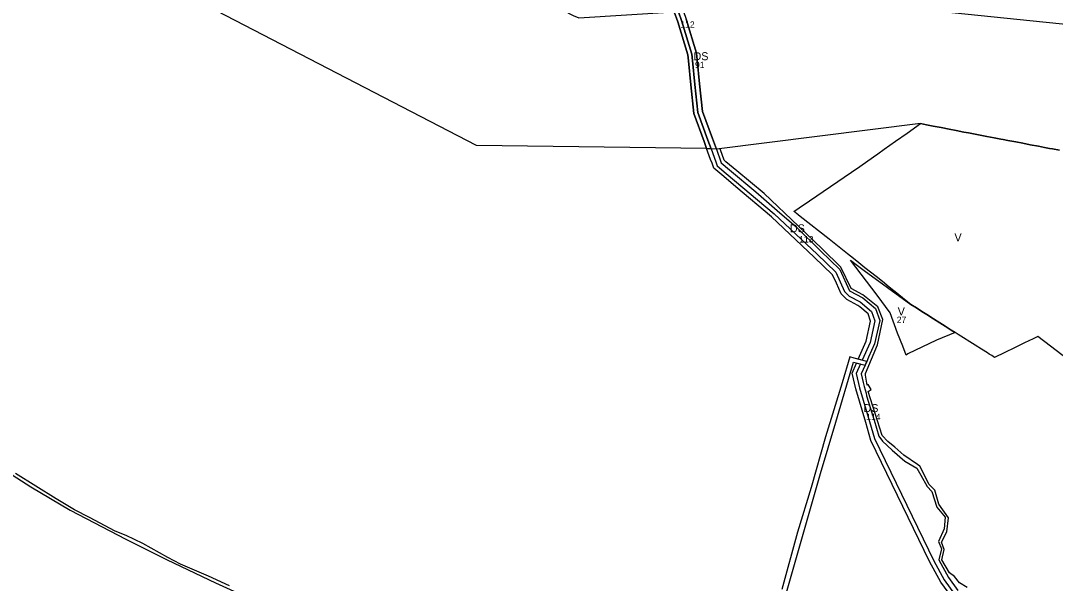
# Model space of a CAD drawing. Extents: x -521621 to -516769, y -1190068 to -1185078.
# Drawn here: x -520820 to -519528, y -1188202 to -1187500 of the extents above; entities that cross this region are included whole.
import ezdxf

# ---------------------------------------------------------------- set-up
doc = ezdxf.new("R2010")
doc.units = 0
for name, color, linetype in [('fpl_id', 7, 'Continuous'), ('v_infrastr_n', 7, 'Continuous'), ('v_infrastr_s', 7, 'Continuous'), ('voda_s', 7, 'Continuous'), ('vyroba_n', 7, 'Continuous'), ('vyroba_s', 7, 'Continuous')]:
    doc.layers.add(name, color=color, linetype=linetype)

msp = doc.modelspace()

# ---------------------------------------------------------------- linework, layer by layer
at = {"layer": 'v_infrastr_n'}
for points in [[(-520849, -1187150.2), (-520815.2, -1187153.9), (-520804.3, -1187155.1), (-520795.3, -1187156), (-520786.2, -1187157), (-520784.9, -1187157.2), (-520159, -1187477.9), (-520132.3, -1187491.8), (-520130, -1187493), (-520122.9, -1187496.1), (-520003.6, -1187488.8), (-519999.4, -1187501.1), (-519986.8, -1187542.4), (-519985.9, -1187549.9), (-519983.1, -1187579.6), (-519979.3, -1187615.3), (-519966.4, -1187650.5), (-519963.3, -1187659), (-520250.8, -1187655.6), (-520830.3, -1187354.9)], [(-519790.9, -1187475.7), (-519421.5, -1187513.5)], [(-519998.5, -1187488.4), (-519994.7, -1187499.6), (-519981.9, -1187541.3), (-519980.9, -1187549.3), (-519978.1, -1187579.2), (-519974.4, -1187614.2), (-519961.7, -1187648.8), (-519957.8, -1187659.5), (-519963.3, -1187659), (-519966.4, -1187650.5), (-519979.3, -1187615.3), (-519983.1, -1187579.6), (-519985.9, -1187549.9), (-519986.8, -1187542.4), (-519999.4, -1187501.1), (-520003.6, -1187488.8)], [(-519522.7, -1187661.3), (-519531.3, -1187659.7), (-519535.2, -1187659), (-519541.3, -1187657.8), (-519548.9, -1187656.4), (-519559.1, -1187654.4), (-519568.5, -1187652.6), (-519577.2, -1187651), (-519587, -1187649.1), (-519592.9, -1187647.9), (-519595.9, -1187647.4), (-519604.1, -1187645.8), (-519613.4, -1187644), (-519623.8, -1187642), (-519636, -1187639.7), (-519642, -1187638.6), (-519651.6, -1187636.7), (-519660.2, -1187635.1), (-519670.3, -1187633.1), (-519680.2, -1187631.2), (-519688.7, -1187629.6), (-519696.3, -1187628.1), (-519951.1, -1187660.2), (-519956.1, -1187646.7), (-519968.5, -1187612.8), (-519972.2, -1187578.6), (-519974.9, -1187548.7), (-519976, -1187540.1), (-519989, -1187497.8)], [(-519656.9, -1188219.1), (-519670.6, -1188200.3), (-519684.7, -1188174.4), (-519758, -1188023.6), (-519764.6, -1188001.2), (-519777.1, -1187959.1), (-519781.6, -1187939.4), (-519776, -1187926.9), (-519771.1, -1187928.1), (-519776.4, -1187939.9), (-519772.2, -1187957.8), (-519759.8, -1187999.7), (-519753.6, -1188021), (-519679.4, -1188173.7), (-519666.4, -1188197.6), (-519653.5, -1188215.3)]]:
    msp.add_lwpolyline(points, dxfattribs=at)
for points in [[(-519992.3, -1187488.1), (-519989, -1187497.8), (-519976, -1187540.1), (-519974.9, -1187548.7), (-519972.2, -1187578.6), (-519968.5, -1187612.8), (-519956.1, -1187646.7), (-519951.1, -1187660.2), (-519957.8, -1187659.5), (-519961.7, -1187648.8), (-519974.4, -1187614.2), (-519978.1, -1187579.2), (-519980.9, -1187549.3), (-519981.9, -1187541.3), (-519994.7, -1187499.6), (-519998.5, -1187488.4)], [(-519957.8, -1187659.5), (-519951.9, -1187675.7), (-519950, -1187680.7), (-519938.7, -1187690.2), (-519879.1, -1187740.9), (-519825.4, -1187791.1), (-519801.9, -1187813.7), (-519790.9, -1187837.6), (-519785.2, -1187843.5), (-519771.6, -1187850.7), (-519757.5, -1187862.4), (-519753.3, -1187874.2), (-519759.1, -1187901.2), (-519769.1, -1187923.5), (-519774, -1187922.2), (-519763.9, -1187899.7), (-519758.5, -1187874.5), (-519761.7, -1187865.3), (-519772, -1187856.8), (-519774.4, -1187854.9), (-519788.2, -1187847.5), (-519795.1, -1187840.5), (-519801.2, -1187827.2), (-519806.1, -1187816.7), (-519828.8, -1187794.7), (-519882.4, -1187744.6), (-519926.7, -1187707), (-519941.9, -1187694.1), (-519954.2, -1187683.7), (-519956.5, -1187677.4), (-519958.3, -1187672.7), (-519963.3, -1187659)]]:
    msp.add_lwpolyline(points, close=True, dxfattribs=at)
at = {"layer": 'v_infrastr_s'}
for points in [[(-519972.8, -1188669.2), (-519973.5, -1188653.5), (-519964.5, -1188604.5), (-519948, -1188528.1), (-519928, -1188459.1), (-519913.3, -1188406), (-519897.6, -1188334.5), (-519884, -1188283.9), (-519860.2, -1188201.7), (-519839.4, -1188128.8), (-519821, -1188064.9), (-519801.9, -1188000.7), (-519780, -1187925.9), (-519765.3, -1187929.6), (-519763.2, -1187925), (-519779.1, -1187921)], [(-519784.5, -1187919.3), (-519794, -1187951.7), (-519814.9, -1188019), (-519832.9, -1188082.4), (-519849.7, -1188138.1), (-519869.3, -1188209.7)], [(-519779.1, -1187921), (-519784.5, -1187919.3)], [(-520849.9, -1188054.2), (-520807.5, -1188081.5), (-520758.2, -1188110.4), (-520688.8, -1188146.6), (-520637.2, -1188172.7), (-520576.6, -1188201.3), (-520525.5, -1188224.7)], [(-520559, -1188204.8), (-520585.4, -1188193.1), (-520620.3, -1188177.8), (-520636.3, -1188169.8), (-520667.4, -1188152.3), (-520688.3, -1188142.3), (-520701.8, -1188136.6), (-520733.9, -1188119.6), (-520752.8, -1188110.2), (-520775.5, -1188096.2), (-520826.5, -1188064.8)]]:
    msp.add_lwpolyline(points, dxfattribs=at)
at = {"layer": 'voda_s'}
for points in [[(-519946, -1187660.7), (-519946.4, -1187659.6), (-519951.1, -1187660.2)], [(-519951.1, -1187660.2), (-519945.5, -1187675.7)], [(-519939.1, -1187675.7), (-519941.2, -1187673.9), (-519946, -1187660.7)], [(-519945.5, -1187675.7), (-519944.9, -1187677.2), (-519934.8, -1187685.7), (-519901.9, -1187713.3), (-519875.1, -1187736.4), (-519851.3, -1187757), (-519821.2, -1187786.7), (-519796.9, -1187810.2), (-519784.7, -1187837), (-519768.2, -1187845.7), (-519752.4, -1187858.8), (-519747.1, -1187873.8), (-519753.4, -1187903.1), (-519760.9, -1187919.7), (-519763.2, -1187925), (-519765.3, -1187929.6), (-519770.1, -1187940.5), (-519767.8, -1187951.4), (-519766.4, -1187956.3), (-519764.2, -1187964.5), (-519763.4, -1187967.8), (-519754.1, -1187998.1), (-519748.2, -1188018), (-519743.4, -1188024.4), (-519731.6, -1188035.5), (-519715.8, -1188049.2), (-519700.7, -1188058.2), (-519695.7, -1188066.7), (-519687.8, -1188080.9), (-519681.8, -1188087.4), (-519675.7, -1188106.7), (-519665.5, -1188119.1), (-519666.7, -1188133.9), (-519673.5, -1188149.5), (-519670.1, -1188158.8), (-519673.1, -1188172.7), (-519661.3, -1188194.4), (-519649.4, -1188210.8)], [(-519638, -1188207.1), (-519647.4, -1188201.3), (-519653.7, -1188193.4), (-519660.1, -1188188.9), (-519669.5, -1188172.4), (-519666.4, -1188159.7), (-519670, -1188150.5), (-519663.2, -1188137.7), (-519661.2, -1188120.1), (-519673.2, -1188103.1), (-519678.3, -1188085.7), (-519685.2, -1188078.7), (-519697.1, -1188055.7), (-519699.8, -1188053.5), (-519716.8, -1188041.7), (-519728.4, -1188031.8), (-519736.9, -1188024.8), (-519743.9, -1188017.4), (-519761.5, -1187962.6), (-519757.6, -1187959.8), (-519761.3, -1187953.8), (-519762.9, -1187954.7), (-519764.9, -1187942.2), (-519764.9, -1187939.8), (-519749.9, -1187904.3), (-519743.3, -1187872.5), (-519749.4, -1187856.8), (-519768.3, -1187841.7), (-519782.6, -1187834), (-519795.7, -1187807.1), (-519819, -1187784.4), (-519848.5, -1187756.2), (-519891.4, -1187715.4), (-519925.6, -1187687), (-519939.1, -1187675.7)]]:
    msp.add_lwpolyline(points, dxfattribs=at)
at = {"layer": 'vyroba_n'}
msp.add_lwpolyline([(-519652.7, -1187889), (-519676.3, -1187898.3), (-519712, -1187915.4), (-519713.9, -1187916.9), (-519718.4, -1187905.7), (-519724.9, -1187889.5), (-519734, -1187864.4), (-519750.2, -1187842.1), (-519783.6, -1187798.4), (-519774.8, -1187805), (-519766.3, -1187811.4), (-519708.1, -1187853.8), (-519701.3, -1187858.1), (-519694.5, -1187862.5), (-519688.1, -1187866.5), (-519679.8, -1187871.8), (-519672.1, -1187876.7), (-519665.3, -1187881), (-519658, -1187885.7)], close=True, dxfattribs=at)
at = {"layer": 'vyroba_s'}
msp.add_lwpolyline([(-519511, -1187923.3), (-519549.5, -1187893.8), (-519555.3, -1187896.6), (-519566.3, -1187901.9), (-519578.8, -1187907.9), (-519590.8, -1187913.7), (-519603.7, -1187919.8), (-519607.1, -1187917.7), (-519610.2, -1187915.7), (-519612.5, -1187914.3), (-519620, -1187909.6), (-519628, -1187904.5), (-519634.6, -1187900.4), (-519642.4, -1187895.5), (-519648.9, -1187891.4), (-519652.7, -1187889), (-519658, -1187885.7), (-519665.3, -1187881), (-519672.1, -1187876.7), (-519679.8, -1187871.8), (-519688.1, -1187866.5), (-519694.5, -1187862.5), (-519701.3, -1187858.1), (-519708.1, -1187853.8), (-519716, -1187847.5), (-519725.9, -1187839.6), (-519735.2, -1187832.2), (-519743.8, -1187825.3), (-519751.5, -1187819.1), (-519758.7, -1187813.4), (-519765.5, -1187807.9), (-519773.2, -1187801.8), (-519780, -1187796.3), (-519787.2, -1187790.6), (-519793.5, -1187785.6), (-519801.9, -1187778.9), (-519810.1, -1187772.5), (-519846.4, -1187743.9), (-519851.5, -1187739.8), (-519852.3, -1187739.1), (-519854.3, -1187737.6), (-519854.3, -1187737.6), (-519847.8, -1187733.2), (-519834.7, -1187724.4), (-519782.4, -1187688.9), (-519772, -1187681.8), (-519754.8, -1187669.7), (-519749.4, -1187665.8), (-519741.4, -1187660.1), (-519727.3, -1187650.1), (-519712.9, -1187639.9), (-519696.3, -1187628.1), (-519688.7, -1187629.6), (-519680.2, -1187631.2), (-519670.3, -1187633.1), (-519660.2, -1187635.1), (-519651.6, -1187636.7), (-519642, -1187638.6), (-519636, -1187639.7), (-519623.8, -1187642), (-519613.4, -1187644), (-519604.1, -1187645.8), (-519595.9, -1187647.4), (-519595.9, -1187647.4), (-519592.9, -1187647.9), (-519587, -1187649.1), (-519577.2, -1187651), (-519568.5, -1187652.6), (-519559.1, -1187654.4), (-519548.9, -1187656.4), (-519541.3, -1187657.8), (-519535.2, -1187659), (-519531.3, -1187659.7), (-519522.7, -1187661.3)], dxfattribs=at)

# ---------------------------------------------------------------- texts
at = {"layer": 'fpl_id'}
for s, p in [('112', (-519996, -1187508.4)), ('91', (-519977.8, -1187558.9)), ('113', (-519847.6, -1187776.5)), ('27', (-519725.8, -1187877)), ('114', (-519764, -1187998.2))]:
    msp.add_text(s, height=8, dxfattribs=at).set_placement(p)
at = {"layer": 'v_infrastr_n'}
for p in [(-519979.6, -1187549), (-519859.2, -1187763.8), (-519767.3, -1187988.2)]:
    msp.add_text('DS', height=10, dxfattribs=at).set_placement(p)
at = {"layer": 'vyroba_n'}
msp.add_text('V', height=10, dxfattribs=at).set_placement((-519724.6, -1187867.5))
at = {"layer": 'vyroba_s'}
msp.add_text('V', height=10, dxfattribs=at).set_placement((-519653.7, -1187775.2))

doc.saveas('drawing.dxf')
